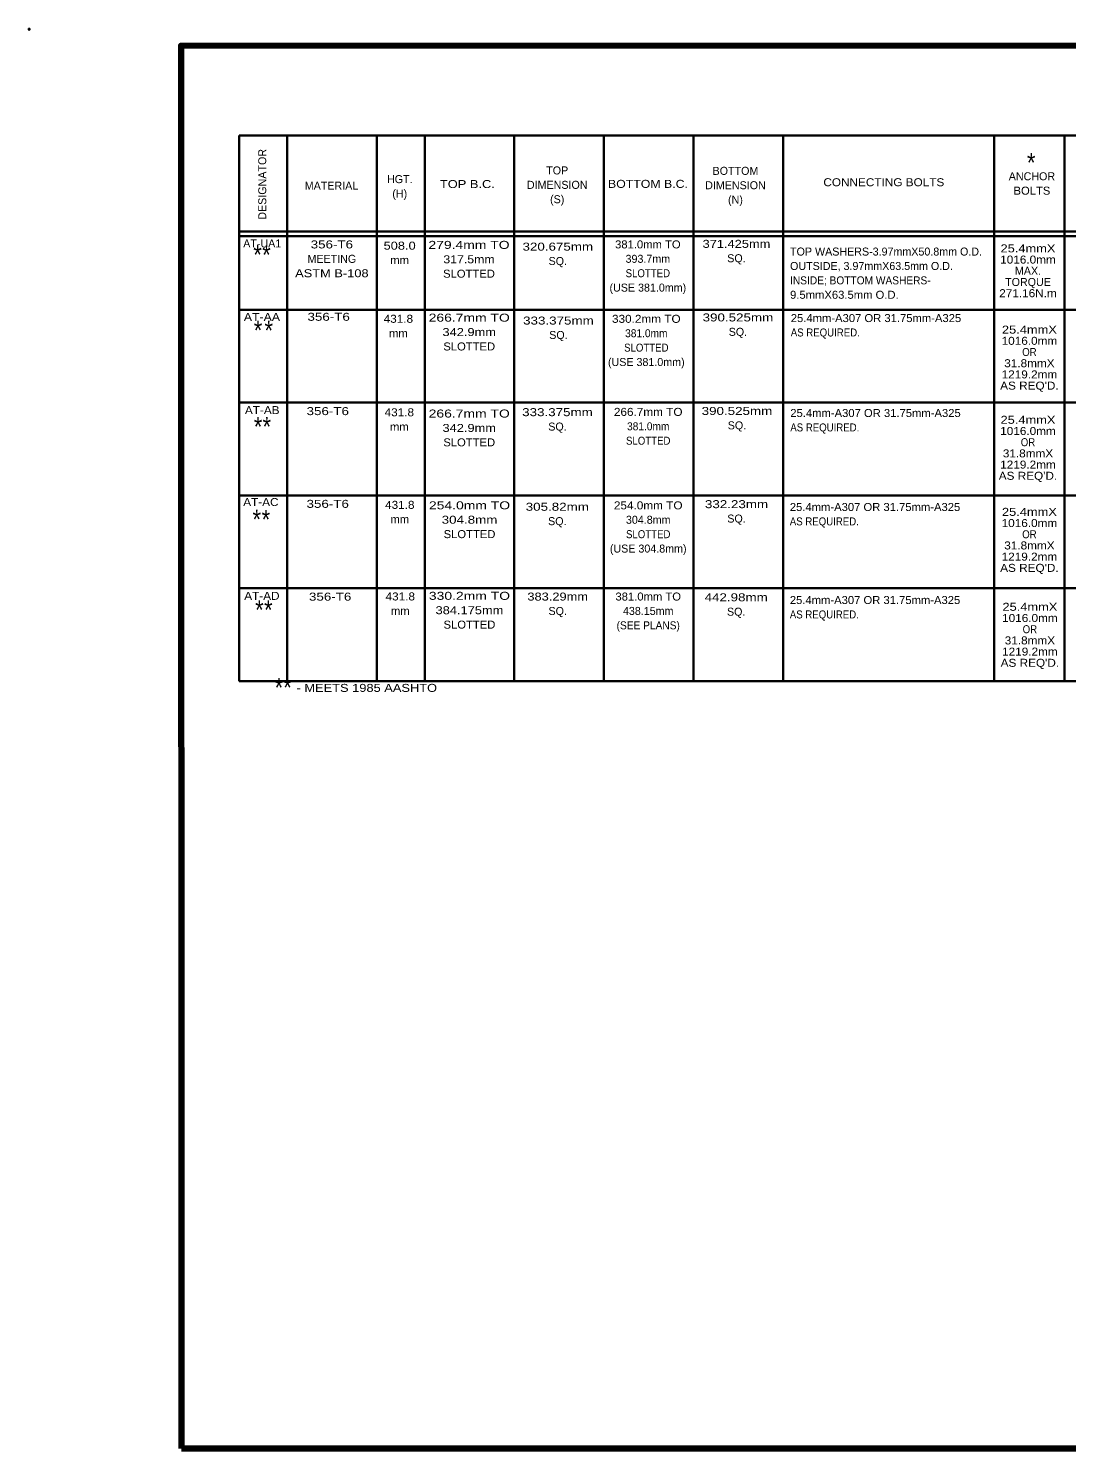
# Model space of a CAD drawing. Extents: x -1228 to -372, y 190 to 734.
# Drawn here: x -1228 to -838, y 201 to 734 of the extents above; entities that cross this region are included whole.
import ezdxf
from ezdxf.enums import TextEntityAlignment as Align

# ---------------------------------------------------------------- set-up
doc = ezdxf.new("R2010")
doc.units = 0
doc.header["$LTSCALE"] = 1.2
doc.header["$PDMODE"] = 32
doc.header["$PDSIZE"] = 0.6
doc.layers.add('1', color=7, linetype='Continuous', lineweight=25)

msp = doc.modelspace()

# ---------------------------------------------------------------- linework, layer by layer
at = {"layer": '1', "lineweight": 35}
for p, q in [((-1148.502, 693.614), (-1148.502, 489.014)), ((-624.102, 693.614), (-1148.502, 693.614)), ((-1130.502, 693.614), (-1130.502, 489.014)), ((-1096.902, 693.614), (-1096.902, 489.014)), ((-1078.902, 693.614), (-1078.902, 489.014)), ((-1045.302, 693.614), (-1045.302, 489.014)), ((-1011.702, 693.614), (-1011.702, 489.014)), ((-978.102, 693.614), (-978.102, 489.014)), ((-944.502, 693.614), (-944.502, 489.014)), ((-865.302, 693.614), (-865.302, 489.014)), ((-838.902, 693.614), (-838.902, 489.014)), ((-624.102, 657.614), (-1148.502, 657.614)), ((-624.102, 655.814), (-1148.502, 655.814)), ((-624.102, 628.214), (-1148.502, 628.214)), ((-624.102, 593.414), (-1148.502, 593.414)), ((-624.102, 558.614), (-1148.502, 558.614)), ((-624.102, 523.814), (-1148.502, 523.814)), ((-624.102, 489.014), (-1148.502, 489.014))]:
    msp.add_line(p, q, dxfattribs=at)
at = {"layer": '1', "lineweight": 158}
msp.add_line((-378.542, 201.223), (-1170.141, 201.223), dxfattribs=at)
msp.add_lwpolyline([(-378.542, 727.323), (-1170.242, 727.223), (-1170.141, 201.223)], dxfattribs=at)
at = {"layer": '1'}
msp.add_point((-1227.242, 733.423), dxfattribs=at)

# ---------------------------------------------------------------- texts
msp.add_text('DESIGNATOR', height=3, rotation=90, dxfattribs=at).set_placement((-1138.321, 661.996))
for s, height, width, p in [('*', 7.2, 0.85, (-852.997, 679.81)), ('*', 7.2, 0.85, (-1143.159, 645.278)), ('*', 7.2, 0.85, (-1139.834, 645.244)), ('INSIDE; BOTTOM WASHERS-', 3, 0.95, (-941.855, 637.748)), ('9.5mmX63.5mm O.D.', 3, 1.05, (-941.855, 632.348)), ('*', 7.2, 0.85, (-1142.997, 616.932)), ('*', 7.2, 0.85, (-1138.973, 616.878)), ('25.4mm-A307 OR 31.75mm-A325', 3, 1.05, (-941.585, 623.612)), ('AS REQUIRED.', 3, 0.9, (-941.585, 618.212)), ('AT-AB', 3, 1.1, (-1146.325, 589.108)), ('*', 7.2, 0.85, (-1142.994, 580.798)), ('*', 7.2, 0.85, (-1139.705, 580.825)), ('25.4mm-A307 OR 31.75mm-A325', 3, 1.05, (-941.764, 588.014)), ('AS REQUIRED.', 3, 0.9, (-941.764, 582.614)), ('25.4mm-A307 OR 31.75mm-A325', 3, 1.05, (-941.942, 552.774)), ('*', 7.2, 0.85, (-1143.469, 546.061)), ('*', 7.2, 0.85, (-1140.043, 546.007)), ('AS REQUIRED.', 3, 0.9, (-941.942, 547.374)), ('*', 7.2, 0.85, (-1142.48, 512.12)), ('*', 7.2, 0.85, (-1139.136, 512.093)), ('25.4mm-A307 OR 31.75mm-A325', 3, 1.05, (-941.942, 517.891)), ('AS REQUIRED.', 3, 0.9, (-941.942, 512.491)), ('*', 7.2, 0.85, (-1135.166, 482.948)), ('*', 7.2, 0.85, (-1131.93, 482.975)), ('- MEETS 1985 AASHTO', 3, 1.2, (-1126.963, 484.945))]:
    msp.add_text(s, height=height, dxfattribs=dict(at, width=width)).set_placement(p)
for s, p in [('TOP', (-1029.192, 678.97)), ('BOTTOM', (-962.334, 678.818)), ('HGT.', (-1088.25, 675.708)), ('DIMENSION', (-1029.192, 673.57)), ('DIMENSION', (-962.334, 673.418)), ('ANCHOR', (-851.137, 676.777)), ('(H)', (-1088.25, 670.308)), ('(S)', (-1029.192, 668.17)), ('(N)', (-962.334, 668.018)), ('AT-UA1', (-1139.827, 651.586)), ('MEETING', (-1113.717, 645.822)), ('SQ.', (-1028.972, 644.995)), ('393.7mm', (-995.198, 645.834)), ('SQ.', (-961.96, 646.044)), ('MAX.', (-852.614, 641.341)), ('TORQUE', (-852.613, 637.141)), ('(USE 381.0mm)', (-995.198, 635.034)), ('SQ.', (-1028.733, 617.279)), ('SQ.', (-961.415, 618.451)), ('(USE 381.0mm)', (-995.771, 607.129)), ('SQ.', (-1029.091, 582.933)), ('SQ.', (-961.773, 583.389)), ('SQ.', (-1029.162, 547.463)), ('304.8mm', (-995.056, 547.986)), ('SQ.', (-961.938, 548.439)), ('(USE 304.8mm)', (-995.056, 537.186)), ('SQ.', (-1029.013, 513.786)), ('438.15mm', (-995.056, 513.802)), ('SQ.', (-962.061, 513.517))]:
    msp.add_text(s, height=3, dxfattribs=at).set_placement(p, align=Align.CENTER)
for s, width, p in [('TOP B.C.', 1.2, (-1062.881, 673.861)), ('BOTTOM B.C.', 1.15, (-995.15, 673.931)), ('CONNECTING BOLTS', 1.1, (-906.683, 674.539)), ('BOLTS', 1.05, (-851.137, 671.377)), ('356-T6', 1.25, (-1113.717, 651.222)), ('508.0', 1.2, (-1088.302, 650.76)), ('279.4mm TO', 1.3, (-1062.281, 651.055)), ('320.675mm', 1.25, (-1028.972, 650.395)), ('381.0mm TO', 1.05, (-995.198, 651.234)), ('371.425mm', 1.2, (-961.96, 651.444)), ('25.4mmX', 1.2, (-852.614, 649.741)), ('mm', 1.05, (-1088.302, 645.361)), ('317.5mm', 1.15, (-1062.281, 645.655)), ('1016.0mm', 1.1, (-852.614, 645.541)), ('ASTM B-108', 1.2, (-1113.717, 640.422)), ('SLOTTED', 1.05, (-1062.281, 640.255)), ('SLOTTED', 0.9, (-995.198, 640.434)), ('271.16N.m', 1.1, (-852.614, 632.941)), ('AT-AA', 1.15, (-1139.949, 624.025)), ('356-T6', 1.25, (-1114.912, 624.093)), ('431.8', 1.1, (-1088.773, 623.347)), ('266.7mm TO', 1.3, (-1062.192, 623.769)), ('333.375mm', 1.25, (-1028.734, 622.679)), ('330.2mm TO', 1.1, (-995.771, 623.329)), ('390.525mm', 1.25, (-961.415, 623.851)), ('mm', 1.05, (-1088.773, 617.947)), ('342.9mm', 1.2, (-1062.192, 618.37)), ('381.0mm', 0.95, (-995.771, 617.929)), ('1016.0mm', 1.1, (-852.077, 615.085)), ('25.4mmX', 1.2, (-852.077, 619.284)), ('SLOTTED', 1.05, (-1062.192, 612.97)), ('SLOTTED', 0.9, (-995.771, 612.529)), ('OR', 0.9, (-852.077, 610.885)), ('31.8mmX', 1.1, (-852.077, 606.685)), ('1219.2mm', 1.1, (-852.077, 602.485)), ("AS REQ'D.", 1.1, (-852.077, 598.284)), ('356-T6', 1.25, (-1115.254, 588.723)), ('431.8', 1.1, (-1088.415, 588.285)), ('333.375mm', 1.25, (-1029.091, 588.333)), ('266.7mm TO', 1.1, (-995.056, 588.43)), ('390.525mm', 1.25, (-961.773, 588.789)), ('266.7mm TO', 1.3, (-1062.192, 587.814)), ('381.0mm', 0.95, (-995.056, 583.03)), ('25.4mmX', 1.2, (-852.613, 585.475)), ('mm', 1.05, (-1088.415, 582.885)), ('342.9mm', 1.2, (-1062.192, 582.414)), ('SLOTTED', 0.9, (-995.056, 577.63)), ('1016.0mm', 1.1, (-852.613, 581.275)), ('SLOTTED', 1.05, (-1062.192, 577.014)), ('31.8mmX', 1.1, (-852.613, 572.875)), ('OR', 0.9, (-852.613, 577.075)), ('1219.2mm', 1.1, (-852.613, 568.675)), ("AS REQ'D.", 1.1, (-852.613, 564.475)), ('AT-AC', 1.1, (-1140.341, 554.636)), ('356-T6', 1.25, (-1115.265, 553.956)), ('431.8', 1.1, (-1088.236, 553.582)), ('254.0mm TO', 1.3, (-1062.08, 553.403)), ('305.82mm', 1.25, (-1029.162, 552.863)), ('254.0mm TO', 1.1, (-995.056, 553.385)), ('332.23mm', 1.25, (-961.938, 553.839)), ('25.4mmX', 1.2, (-852.077, 550.951)), ('mm', 1.05, (-1088.236, 548.182)), ('304.8mm', 1.25, (-1062.08, 548.003)), ('1016.0mm', 1.1, (-852.077, 546.75)), ('SLOTTED', 1.05, (-1062.08, 542.603)), ('SLOTTED', 0.9, (-995.056, 542.586)), ('OR', 0.9, (-852.077, 542.551)), ('31.8mmX', 1.1, (-852.077, 538.351)), ("AS REQ'D.", 1.1, (-852.077, 529.951)), ('1219.2mm', 1.1, (-852.077, 534.151)), ('AT-AD', 1.1, (-1139.957, 519.463)), ('356-T6', 1.25, (-1114.357, 519.159)), ('431.8', 1.1, (-1088.057, 519.236)), ('330.2mm TO', 1.3, (-1062.108, 519.469)), ('383.29mm', 1.2, (-1029.013, 519.186)), ('381.0mm TO', 1.05, (-995.056, 519.202)), ('442.98mm', 1.25, (-962.061, 518.917)), ('384.175mm', 1.2, (-1062.108, 514.068)), ('25.4mmX', 1.2, (-851.898, 515.353)), ('mm', 1.05, (-1088.058, 513.836)), ('SLOTTED', 1.05, (-1062.108, 508.669)), ('(SEE PLANS)', 0.95, (-995.056, 508.402)), ('1016.0mm', 1.1, (-851.898, 511.153)), ('OR', 0.9, (-851.898, 506.953)), ('1219.2mm', 1.1, (-851.898, 498.553)), ('31.8mmX', 1.1, (-851.898, 502.752)), ("AS REQ'D.", 1.1, (-851.898, 494.353))]:
    msp.add_text(s, height=3, dxfattribs=dict(at, width=width)).set_placement(p, align=Align.CENTER)
for s, p in [('MATERIAL', (-1123.881, 673.25)), ('TOP WASHERS-3.97mmX50.8mm O.D.', (-941.855, 648.548)), ('OUTSIDE, 3.97mmX63.5mm O.D.', (-941.855, 643.148))]:
    msp.add_text(s, height=3, dxfattribs=at).set_placement(p)

doc.saveas('drawing.dxf')
